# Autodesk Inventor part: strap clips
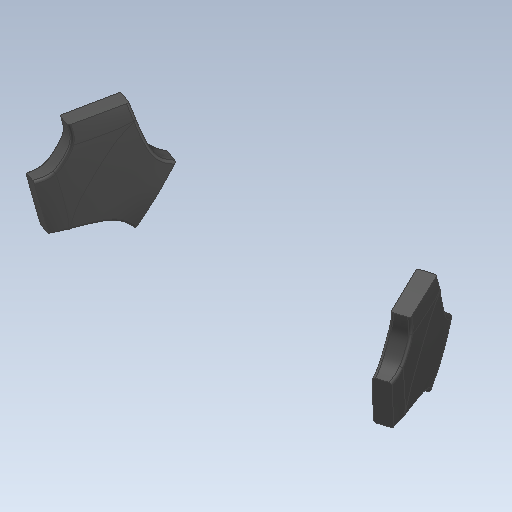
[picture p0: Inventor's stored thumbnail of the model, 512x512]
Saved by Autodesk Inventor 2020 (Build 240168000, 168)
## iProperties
Created: 2021-10
Part Number: strap clips
Material: Steel
Document SubType Name: Modeling
Designer: bruno
Density: 7.85 g/cm^3
Appearance: Par défaut
Author: bruno
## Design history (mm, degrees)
feature "Body1"
feature "Body2"
node "Solide1"
node "Solide2"
